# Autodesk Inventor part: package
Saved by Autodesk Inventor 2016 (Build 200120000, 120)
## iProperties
Created: 2016-09
Part Number: package
Material: Generic
Document SubType Name: Modeling
Designer: Administrator
Appearance: Generic
Author: Administrator
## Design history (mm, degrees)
feature "Body1"
body "Solid1"
